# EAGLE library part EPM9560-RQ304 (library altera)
EPM9560 MAX 9000 family
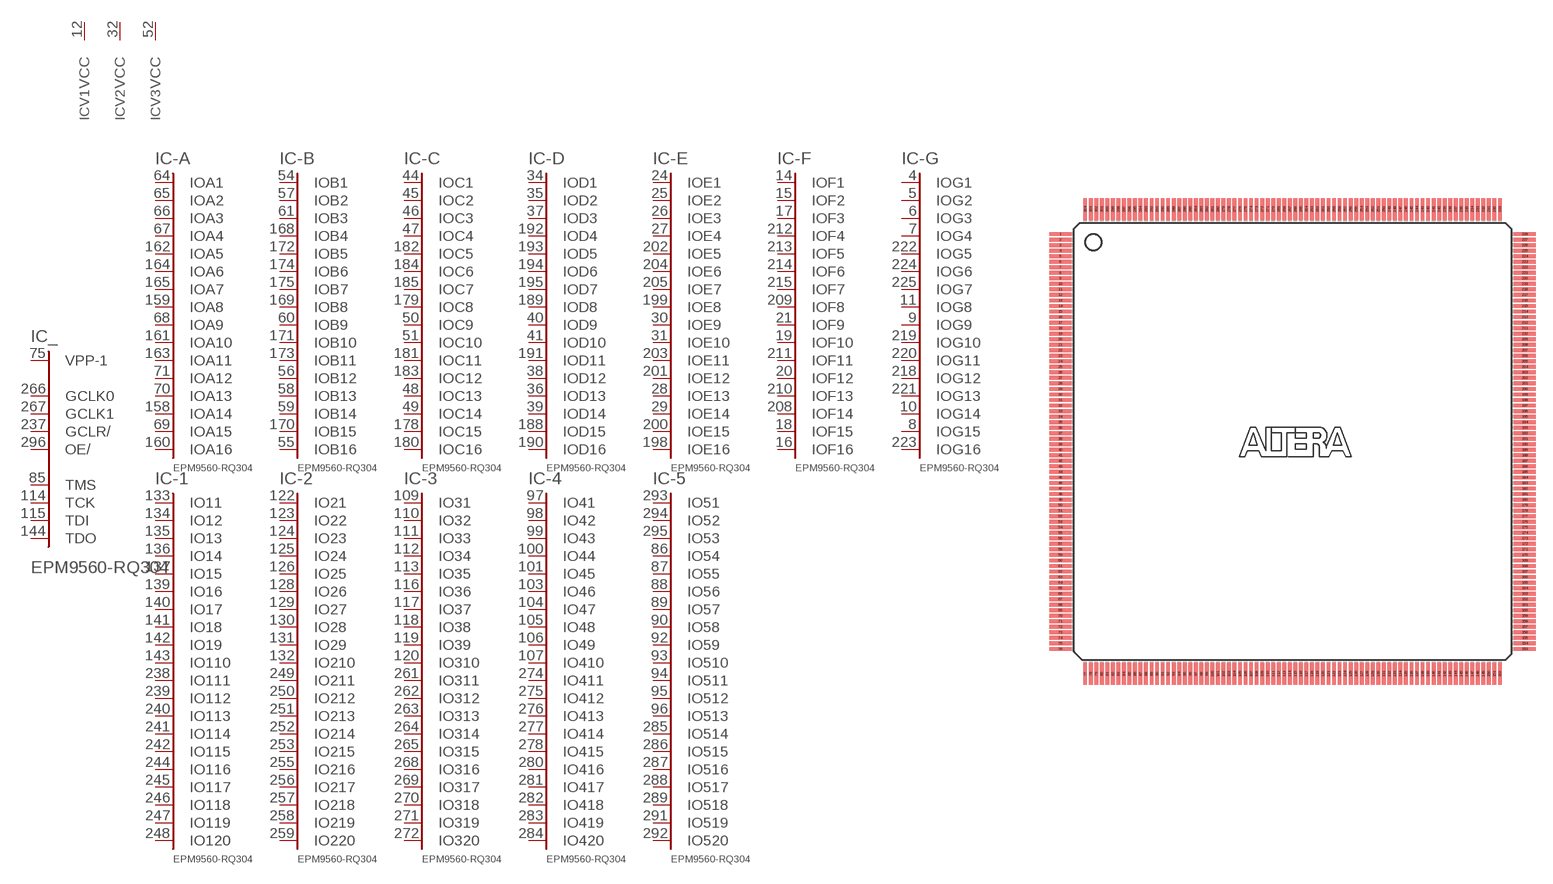
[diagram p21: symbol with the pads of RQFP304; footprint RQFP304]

Designator prefix IC; gates _=9560C356 -A=A16-0 -B=B16-0 -C=C16-0 -D=D16-0 -E=E16-0 -F=F16-0 -G=G16-0 -1=IO120 -2=IO220 -3=IO320 -4=IO420 -5=IO520 V1=VCCINT V2=VCCINT V3=VCCINT V4=VCCINT V5=VCCINT V6=VCCINT V7=VCCINT V8=VCCINT VO1=VCCIO VO2=VCCIO VO3=VCCIO VO4=VCCIO VO5=VCCIO VO6=VCCIO VO7=VCCIO VO8=VCCIO VO9=VCCIO VO10=VCCIO VO11=VCCIO VO12=VCCIO VO13=VCCIO VO14=VCCIO G1=GND G2=GND G3=GND G4=GND G5=GND G6=GND G7=GND G8=GND G9=GND G10=GND G11=GND G12=GND G13=GND G14=GND G15=GND G16=GND G17=GND G18=GND G19=GND G20=GND G21=GND G22=GND NC1=NC NC2=NC NC3=NC NC4=NC NC5=NC NC6=NC NC7=NC NC8=NC NC9=NC NC10=NC NC11=NC NC12=NC NC13=NC NC14=NC NC15=NC NC16=NC NC17=NC NC18=NC NC19=NC NC20=NC NC21=NC NC22=NC NC23=NC NC24=NC NC25=NC NC26=NC NC27=NC NC28=NC NC29=NC NC30=NC NC31=NC NC32=NC NC33=NC NC34=NC NC35=NC NC36=NC NC37=NC NC38=NC NC39=NC

## EPM9560-RQ304 (OC_FARNELL: unknown; OC_NEWARK: unknown)  [RQFP304]
1  NC1:NC  nc
2  NC2:NC  nc
3  VO1:VCCIO  pwr
4  -G:IOG1
5  -G:IOG2
6  -G:IOG3
7  -G:IOG4
8  -G:IOG15
9  -G:IOG9
10  -G:IOG14
11  -G:IOG8
12  V1:VCC  pwr
13  G1:GND  pwr
14  -F:IOF1
15  -F:IOF2
16  -F:IOF16
17  -F:IOF3
18  -F:IOF15
19  -F:IOF10
20  -F:IOF12
21  -F:IOF9
22  G2:GND  pwr
23  VO2:VCCIO  pwr
24  -E:IOE1
25  -E:IOE2
26  -E:IOE3
27  -E:IOE4
28  -E:IOE13
29  -E:IOE14
30  -E:IOE9
31  -E:IOE10
32  V2:VCC  pwr
33  G3:GND  pwr
34  -D:IOD1
35  -D:IOD2
36  -D:IOD13
37  -D:IOD3
38  -D:IOD12
39  -D:IOD14
40  -D:IOD9
41  -D:IOD10
42  G4:GND  pwr
43  VO3:VCCIO  pwr
44  -C:IOC1
45  -C:IOC2
46  -C:IOC3
47  -C:IOC4
48  -C:IOC13
49  -C:IOC14
50  -C:IOC9
51  -C:IOC10
52  V3:VCC  pwr
53  G5:GND  pwr
54  -B:IOB1
55  -B:IOB16
56  -B:IOB12
57  -B:IOB2
58  -B:IOB13
59  -B:IOB14
60  -B:IOB9
61  -B:IOB3
62  G6:GND  pwr
63  VO4:VCCIO  pwr
64  -A:IOA1
65  -A:IOA2
66  -A:IOA3
67  -A:IOA4
68  -A:IOA9
69  -A:IOA15
70  -A:IOA13
71  -A:IOA12
72  V4:VCC  pwr
73  G7:GND  pwr
74  G8:GND  pwr
75  _:VPP-1  in
76  NC3:NC  nc
77  NC4:NC  nc
78  NC5:NC  nc
79  NC6:NC  nc
80  NC7:NC  nc
81  NC8:NC  nc
82  NC9:NC  nc
83  NC10:NC  nc
84  NC11:NC  nc
85  _:TMS
86  -5:IO54
87  -5:IO55
88  -5:IO56
89  -5:IO57
90  -5:IO58
91  VO5:VCCIO  pwr
92  -5:IO59
93  -5:IO510
94  -5:IO511
95  -5:IO512
96  -5:IO513
97  -4:IO41
98  -4:IO42
99  -4:IO43
100  -4:IO44
101  -4:IO45
102  G9:GND  pwr
103  -4:IO46
104  -4:IO47
105  -4:IO48
106  -4:IO49
107  -4:IO410
108  VO6:VCCIO  pwr
109  -3:IO31
110  -3:IO32
111  -3:IO33
112  -3:IO34
113  -3:IO35
114  _:TCK
115  _:TDI
116  -3:IO36
117  -3:IO37
118  -3:IO38
119  -3:IO39
120  -3:IO310
121  G10:GND  pwr
122  -2:IO21
123  -2:IO22
124  -2:IO23
125  -2:IO24
126  -2:IO25
127  VO7:VCCIO  pwr
128  -2:IO26
129  -2:IO27
130  -2:IO28
131  -2:IO29
132  -2:IO210
133  -1:IO11
134  -1:IO12
135  -1:IO13
136  -1:IO14
137  -1:IO15
138  G11:GND  pwr
139  -1:IO16
140  -1:IO17
141  -1:IO18
142  -1:IO19
143  -1:IO110
144  _:TDO
145  NC12:NC  nc
146  NC13:NC  nc
147  NC14:NC  nc
148  NC15:NC  nc
149  NC16:NC  nc
150  NC17:NC  nc
151  NC18:NC  nc
152  NC19:NC  nc
153  NC20:NC  nc
154  NC21:NC  nc
155  G12:GND  pwr
156  VO8:VCCIO  pwr
157  V5:VCC  pwr
158  -A:IOA14
159  -A:IOA8
160  -A:IOA16
161  -A:IOA10
162  -A:IOA5
163  -A:IOA11
164  -A:IOA6
165  -A:IOA7
166  G13:GND  pwr
167  G14:GND  pwr
168  -B:IOB4
169  -B:IOB8
170  -B:IOB15
171  -B:IOB10
172  -B:IOB5
173  -B:IOB11
174  -B:IOB6
175  -B:IOB7
176  VO9:VCCIO  pwr
177  V6:VCC  pwr
178  -C:IOC15
179  -C:IOC8
180  -C:IOC16
181  -C:IOC11
182  -C:IOC5
183  -C:IOC12
184  -C:IOC6
185  -C:IOC7
186  G15:GND  pwr
187  G16:GND  pwr
188  -D:IOD15
189  -D:IOD8
190  -D:IOD16
191  -D:IOD11
192  -D:IOD4
193  -D:IOD5
194  -D:IOD6
195  -D:IOD7
196  VO10:VCCIO  pwr
197  V7:VCC  pwr
198  -E:IOE16
199  -E:IOE8
200  -E:IOE15
201  -E:IOE12
202  -E:IOE5
203  -E:IOE11
204  -E:IOE6
205  -E:IOE7
206  G17:GND  pwr
207  G18:GND  pwr
208  -F:IOF14
209  -F:IOF8
210  -F:IOF13
211  -F:IOF11
212  -F:IOF4
213  -F:IOF5
214  -F:IOF6
215  -F:IOF7
216  VO11:VCCIO  pwr
217  V8:VCC  pwr
218  -G:IOG12
219  -G:IOG10
220  -G:IOG11
221  -G:IOG13
222  -G:IOG5
223  -G:IOG16
224  -G:IOG6
225  -G:IOG7
226  G19:GND  pwr
227  NC22:NC  nc
228  NC23:NC  nc
229  NC24:NC  nc
230  NC25:NC  nc
231  NC26:NC  nc
232  NC27:NC  nc
233  NC28:NC  nc
234  NC29:NC  nc
235  NC30:NC  nc
236  NC31:NC  nc
237  _:GCLR/  in
238  -1:IO111
239  -1:IO112
240  -1:IO113
241  -1:IO114
242  -1:IO115
243  VO12:VCCIO  pwr
244  -1:IO116
245  -1:IO117
246  -1:IO118
247  -1:IO119
248  -1:IO120
249  -2:IO211
250  -2:IO212
251  -2:IO213
252  -2:IO214
253  -2:IO215
254  G20:GND  pwr
255  -2:IO216
256  -2:IO217
257  -2:IO218
258  -2:IO219
259  -2:IO220
260  VO13:VCCIO  pwr
261  -3:IO311
262  -3:IO312
263  -3:IO313
264  -3:IO314
265  -3:IO315
266  _:GCLK0  in
267  _:GCLK1  in
268  -3:IO316
269  -3:IO317
270  -3:IO318
271  -3:IO319
272  -3:IO320
273  G21:GND  pwr
274  -4:IO411
275  -4:IO412
276  -4:IO413
277  -4:IO414
278  -4:IO415
279  VO14:VCCIO  pwr
280  -4:IO416
281  -4:IO417
282  -4:IO418
283  -4:IO419
284  -4:IO420
285  -5:IO514
286  -5:IO515
287  -5:IO516
288  -5:IO517
289  -5:IO518
290  G22:GND  pwr
291  -5:IO519
292  -5:IO520
293  -5:IO51
294  -5:IO52
295  -5:IO53
296  _:OE/  in
297  NC32:NC  nc
298  NC33:NC  nc
299  NC34:NC  nc
300  NC35:NC  nc
301  NC36:NC  nc
302  NC37:NC  nc
303  NC38:NC  nc
304  NC39:NC  nc

## Footprint RQFP304 (pad centres in mm)
Power Quad Flat Pack
smd 2 x 0.35: 1 -21,18.75; 2 -21,18.25; 3 -21,17.75; 4 -21,17.25; 5 -21,16.75; 6 -21,16.25; 7 -21,15.75; 8 -21,15.25; 9 -21,14.75; 10 -21,14.25; 11 -21,13.75; 12 -21,13.25; 13 -21,12.75; 14 -21,12.25; 15 -21,11.75; 16 -21,11.25; 17 -21,10.75; 18 -21,10.25; 19 -21,9.75; 20 -21,9.25; 21 -21,8.75; 22 -21,8.25; 23 -21,7.75; 24 -21,7.25; 25 -21,6.75; 26 -21,6.25; 27 -21,5.75; 28 -21,5.25; 29 -21,4.75; 30 -21,4.25; 31 -21,3.75; 32 -21,3.25; 33 -21,2.75; 34 -21,2.25; 35 -21,1.75; 36 -21,1.25; 37 -21,0.75; 38 -21,0.25; 39 -21,-0.25; 40 -21,-0.75; 41 -21,-1.25; 42 -21,-1.75; 43 -21,-2.25; 44 -21,-2.75; 45 -21,-3.25; 46 -21,-3.75; 47 -21,-4.25; 48 -21,-4.75; 49 -21,-5.25; 50 -21,-5.75; 51 -21,-6.25; 52 -21,-6.75; 53 -21,-7.25; 54 -21,-7.75; 55 -21,-8.25; 56 -21,-8.75; 57 -21,-9.25; 58 -21,-9.75; 59 -21,-10.25; 60 -21,-10.75; 61 -21,-11.25; 62 -21,-11.75; 63 -21,-12.25; 64 -21,-12.75; 65 -21,-13.25; 66 -21,-13.75; 67 -21,-14.25; 68 -21,-14.75; 69 -21,-15.25; 70 -21,-15.75; 71 -21,-16.25; 72 -21,-16.75; 73 -21,-17.25; 74 -21,-17.75; 75 -21,-18.25; 76 -21,-18.75; 153 21,-18.75; 154 21,-18.25; 155 21,-17.75; 156 21,-17.25; 157 21,-16.75; 158 21,-16.25; 159 21,-15.75; 160 21,-15.25; 161 21,-14.75; 162 21,-14.25; 163 21,-13.75; 164 21,-13.25; 165 21,-12.75; 166 21,-12.25; 167 21,-11.75; 168 21,-11.25; 169 21,-10.75; 170 21,-10.25; 171 21,-9.75; 172 21,-9.25; 173 21,-8.75; 174 21,-8.25; 175 21,-7.75; 176 21,-7.25; 177 21,-6.75; 178 21,-6.25; 179 21,-5.75; 180 21,-5.25; 181 21,-4.75; 182 21,-4.25; 183 21,-3.75; 184 21,-3.25; 185 21,-2.75; 186 21,-2.25; 187 21,-1.75; 188 21,-1.25; 189 21,-0.75; 190 21,-0.25; 191 21,0.25; 192 21,0.75; 193 21,1.25; 194 21,1.75; 195 21,2.25; 196 21,2.75; 197 21,3.25; 198 21,3.75; 199 21,4.25; 200 21,4.75; 201 21,5.25; 202 21,5.75; 203 21,6.25; 204 21,6.75; 205 21,7.25; 206 21,7.75; 207 21,8.25; 208 21,8.75; 209 21,9.25; 210 21,9.75; 211 21,10.25; 212 21,10.75; 213 21,11.25; 214 21,11.75; 215 21,12.25; 216 21,12.75; 217 21,13.25; 218 21,13.75; 219 21,14.25; 220 21,14.75; 221 21,15.25; 222 21,15.75; 223 21,16.25; 224 21,16.75; 225 21,17.25; 226 21,17.75; 227 21,18.25; 228 21,18.75
smd 0.35 x 2: 77 -18.75,-21; 78 -18.25,-21; 79 -17.75,-21; 80 -17.25,-21; 81 -16.75,-21; 82 -16.25,-21; 83 -15.75,-21; 84 -15.25,-21; 85 -14.75,-21; 86 -14.25,-21; 87 -13.75,-21; 88 -13.25,-21; 89 -12.75,-21; 90 -12.25,-21; 91 -11.75,-21; 92 -11.25,-21; 93 -10.75,-21; 94 -10.25,-21; 95 -9.75,-21; 96 -9.25,-21; 97 -8.75,-21; 98 -8.25,-21; 99 -7.75,-21; 100 -7.25,-21; 101 -6.75,-21; 102 -6.25,-21; 103 -5.75,-21; 104 -5.25,-21; 105 -4.75,-21; 106 -4.25,-21; 107 -3.75,-21; 108 -3.25,-21; 109 -2.75,-21; 110 -2.25,-21; 111 -1.75,-21; 112 -1.25,-21; 113 -0.75,-21; 114 -0.25,-21; 115 0.25,-21; 116 0.75,-21; 117 1.25,-21; 118 1.75,-21; 119 2.25,-21; 120 2.75,-21; 121 3.25,-21; 122 3.75,-21; 123 4.25,-21; 124 4.75,-21; 125 5.25,-21; 126 5.75,-21; 127 6.25,-21; 128 6.75,-21; 129 7.25,-21; 130 7.75,-21; 131 8.25,-21; 132 8.75,-21; 133 9.25,-21; 134 9.75,-21; 135 10.25,-21; 136 10.75,-21; 137 11.25,-21; 138 11.75,-21; 139 12.25,-21; 140 12.75,-21; 141 13.25,-21; 142 13.75,-21; 143 14.25,-21; 144 14.75,-21; 145 15.25,-21; 146 15.75,-21; 147 16.25,-21; 148 16.75,-21; 149 17.25,-21; 150 17.75,-21; 151 18.25,-21; 152 18.75,-21; 229 18.75,21; 230 18.25,21; 231 17.75,21; 232 17.25,21; 233 16.75,21; 234 16.25,21; 235 15.75,21; 236 15.25,21; 237 14.75,21; 238 14.25,21; 239 13.75,21; 240 13.25,21; 241 12.75,21; 242 12.25,21; 243 11.75,21; 244 11.25,21; 245 10.75,21; 246 10.25,21; 247 9.75,21; 248 9.25,21; 249 8.75,21; 250 8.25,21; 251 7.75,21; 252 7.25,21; 253 6.75,21; 254 6.25,21; 255 5.75,21; 256 5.25,21; 257 4.75,21; 258 4.25,21; 259 3.75,21; 260 3.25,21; 261 2.75,21; 262 2.25,21; 263 1.75,21; 264 1.25,21; 265 0.75,21; 266 0.25,21; 267 -0.25,21; 268 -0.75,21; 269 -1.25,21; 270 -1.75,21; 271 -2.25,21; 272 -2.75,21; 273 -3.25,21; 274 -3.75,21; 275 -4.25,21; 276 -4.75,21; 277 -5.25,21; 278 -5.75,21; 279 -6.25,21; 280 -6.75,21; 281 -7.25,21; 282 -7.75,21; 283 -8.25,21; 284 -8.75,21; 285 -9.25,21; 286 -9.75,21; 287 -10.25,21; 288 -10.75,21; 289 -11.25,21; 290 -11.75,21; 291 -12.25,21; 292 -12.75,21; 293 -13.25,21; 294 -13.75,21; 295 -14.25,21; 296 -14.75,21; 297 -15.25,21; 298 -15.75,21; 299 -16.25,21; 300 -16.75,21; 301 -17.25,21; 302 -17.75,21; 303 -18.25,21; 304 -18.75,21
